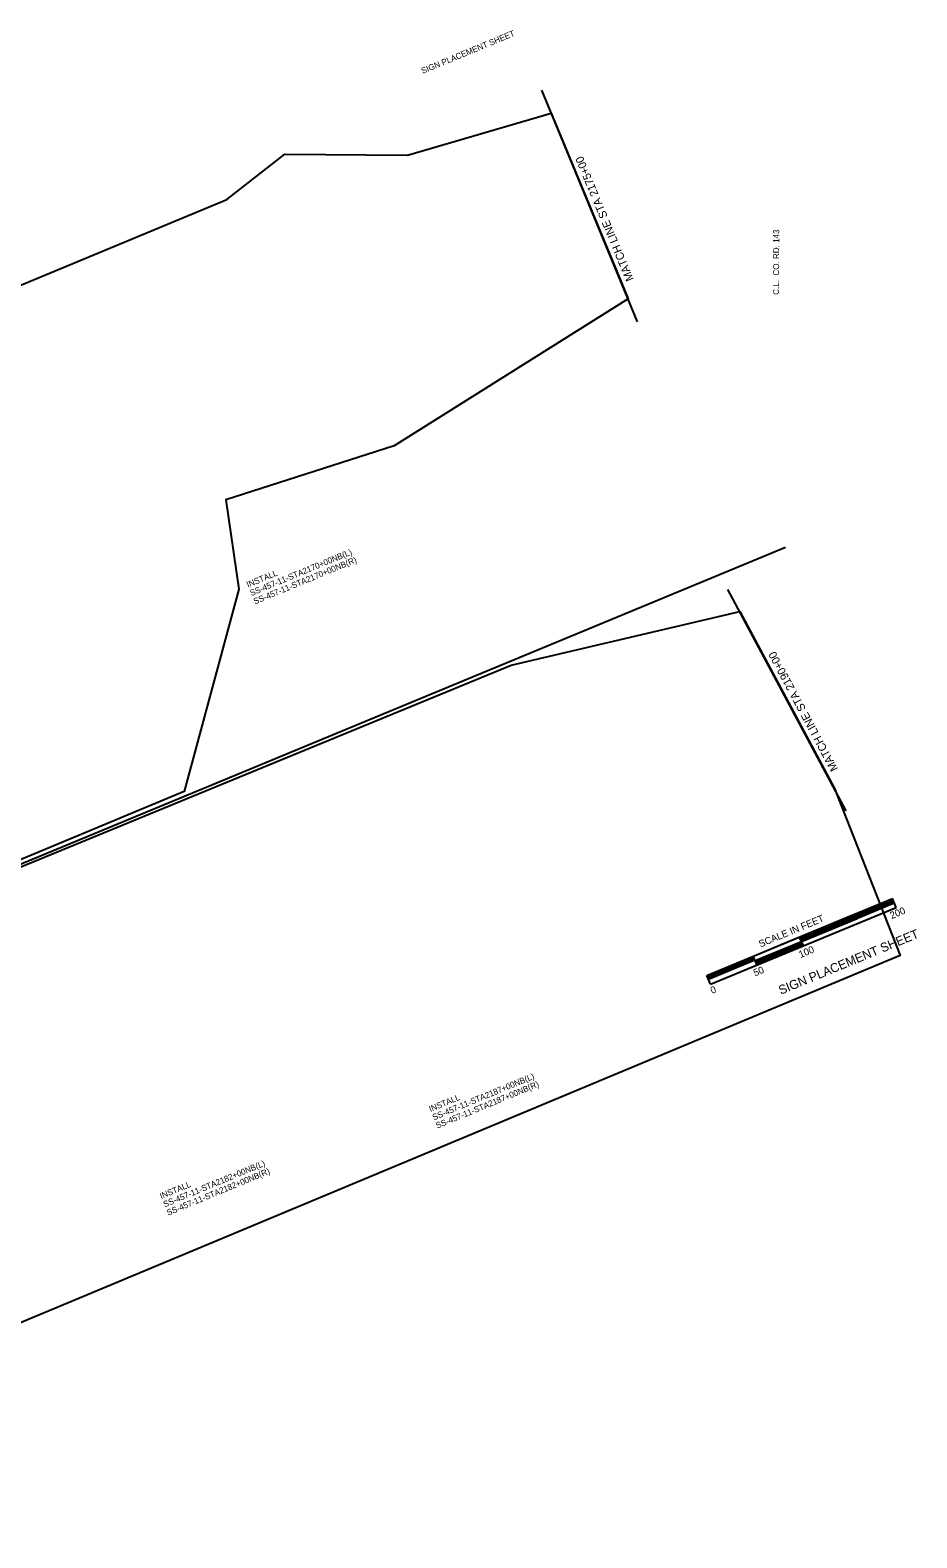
# Model space of a CAD drawing. Extents: x 1721726 to 1723493, y 767411 to 768913.
# Drawn here: x 1722610 to 1723493, y 767411 to 768913 of the extents above; entities that cross this region are included whole.
import ezdxf

# ---------------------------------------------------------------- set-up
doc = ezdxf.new("R2010")
doc.units = 0
for name, color, linetype in [('1', 7, 'Continuous'), ('60', 7, 'Continuous'), ('G-ANNO-TEXT', 7, 'Continuous'), ('G-Border-Sheet', 7, 'Continuous'), ('Level 10', 7, 'Continuous'), ('Plan Notes', 7, 'Continuous'), ('R_Annotation', 7, 'Continuous'), ('R_Draft', 7, 'Continuous')]:
    doc.layers.add(name, color=color, linetype=linetype)

msp = doc.modelspace()

# ---------------------------------------------------------------- linework, layer by layer
at = {"layer": '1'}
for points in [[(1721928.1, 767806.8), (1721819.6, 768071.9), (1721743, 768256.7), (1721726.5, 768296.6), (1722805.8, 768744.9), (1722863.6, 768790), (1722985.6, 768789), (1723128.8, 768830.7), (1723205.4, 768645.9), (1722972.5, 768499.4), (1722804.6, 768445.4), (1722817.5, 768356.5), (1722763.1, 768155)], [(1722086.8, 767411.4), (1722041, 767523), (1721945.3, 767754), (1721924.4, 767801.9), (1723089, 768280.7), (1723316.6, 768334.2), (1723410.9, 768157.8), (1723476.5, 767991.7)]]:
    msp.add_lwpolyline(points, close=True, dxfattribs=at)
at = {"layer": 'G-Border-Sheet'}
msp.add_line((1721888.2, 767787.7), (1723362.1, 768398.3), dxfattribs=at)
at = {"layer": 'Level 10'}
for p, q in [((1723357.8, 768002.4), (1723468.7, 768048.3)), ((1723376.6, 768009.3), (1723469, 768047.6)), ((1723376.9, 768008.6), (1723469.3, 768046.8)), ((1723377.2, 768007.8), (1723469.6, 768046.1)), ((1723377.5, 768007.1), (1723469.9, 768045.4)), ((1723377.8, 768006.4), (1723470.2, 768044.6)), ((1723378.1, 768005.6), (1723470.5, 768043.9)), ((1723472.4, 768039.4), (1723468.7, 768048.3)), ((1723283.9, 767971.8), (1723431.7, 768033)), ((1723287.6, 767962.9), (1723472.3, 768039.4)), ((1723378.1, 768005.6), (1723433.5, 768028.6)), ((1723331.9, 767986.5), (1723378.1, 768005.6)), ((1723332.2, 767985.7), (1723378.4, 768004.9)), ((1723332.5, 767985), (1723378.7, 768004.1)), ((1723332.8, 767984.3), (1723379, 768003.4)), ((1723333.2, 767983.5), (1723379.3, 768002.7)), ((1723333.5, 767982.8), (1723379.6, 768001.9)), ((1723380, 768001.2), (1723376.3, 768010)), ((1723283.9, 767971.8), (1723320.8, 767987.1)), ((1723284.2, 767971), (1723330.4, 767990.2)), ((1723284.5, 767970.3), (1723330.7, 767989.4)), ((1723284.8, 767969.6), (1723331, 767988.7)), ((1723285.1, 767968.8), (1723331.3, 767988)), ((1723285.4, 767968.1), (1723331.6, 767987.2)), ((1723324.5, 767978.2), (1723361.5, 767993.5)), ((1723333.8, 767982), (1723330.1, 767990.9)), ((1723287.6, 767962.9), (1723283.9, 767971.8))]:
    msp.add_line(p, q, dxfattribs=at)
at = {"layer": 'Plan Notes'}
for p, q in [((1723214.9, 768622.8), (1723119.3, 768853.8)), ((1723422.7, 768135.7), (1723304.9, 768356.2))]:
    msp.add_line(p, q, dxfattribs=at)

# ---------------------------------------------------------------- texts
at = {"layer": '60'}
msp.add_text('SIGN PLACEMENT SHEET', height=9, rotation=22.5, dxfattribs=at).set_placement((1723357.5, 767952.4))
at = {"layer": 'G-ANNO-TEXT'}
msp.add_text('SIGN PLACEMENT SHEET', height=6, rotation=22.5, dxfattribs=at).set_placement((1723000.8, 768869.8))
at = {"layer": 'Level 10'}
for s, height, p in [('SCALE IN FEET', 7.001, (1723337.3, 767999.5)), ('200', 7, (1723467.9, 768027.8)), ('100', 7, (1723377.1, 767989)), ('50', 7, (1723331.9, 767970.7)), ('0', 7, (1723289.1, 767953.2))]:
    msp.add_text(s, height=height, rotation=22.5003, dxfattribs=at).set_placement(p)
at = {"layer": 'Plan Notes'}
for s, rotation, p in [('MATCH LINE STA 2175+00', 112.5, (1723211.1, 768665.3)), ('MATCH LINE STA 2190+00', 118.1201, (1723414.7, 768177.6))]:
    msp.add_text(s, height=8, rotation=rotation, dxfattribs=at).set_placement(p)
at = {"layer": 'R_Annotation'}
for s, p in [('SS-457-11-STA2170+00NB(L)', (1722830.2, 768349.6)), ('INSTALL', (1722826.8, 768358)), ('SS-457-11-STA2170+00NB(R)', (1722833.7, 768341.3)), ('SS-457-11-STA2187+00NB(L)', (1723011.9, 767827.3)), ('SS-457-11-STA2187+00NB(R)', (1723015.3, 767819)), ('INSTALL', (1723008.5, 767835.6)), ('SS-457-11-STA2182+00NB(L)', (1722743.8, 767740.6)), ('SS-457-11-STA2182+00NB(R)', (1722747.2, 767732.3)), ('INSTALL', (1722740.4, 767748.9))]:
    msp.add_text(s, height=6, rotation=22.5, dxfattribs=at).set_placement(p)
at = {"layer": 'R_Draft'}
msp.add_text('C.L.  CO. RD. 143', height=6, rotation=89.9023, dxfattribs=at).set_placement((1723355.8, 768649.8))

doc.saveas('drawing.dxf')
